Omron CX-Programmer project NuevoProyecto (CX-Programmer 9.50)

# PLC NewPLC1: CQM1 CPU21

## Global symbols (name address type ; comment)
15.00 BOOL  ; CNT<3
15.01 BOOL  ; CNT=3

## Program P9_2 (no task)
Local symbols
CNT 15.00 BOOL  ; Salida contador
DN1 0.01 BOOL  ; Detector de nivel inferior depósito A
DN2 0.02 BOOL  ; Detector de nivel superior depósito A
DN3 0.03 BOOL  ; Detector de nivel inferior depósito B
DN4 0.04 BOOL  ; Detector de nivel superior depósito B
Etapa_0 10.00 BOOL
Etapa_1 10.01 BOOL
Etapa_10 10.10 BOOL
Etapa_11 10.11 BOOL
Etapa_2 10.02 BOOL
Etapa_3 10.03 BOOL
Etapa_4 10.04 BOOL
Etapa_5 10.05 BOOL
Etapa_6 10.06 BOOL
Etapa_7 10.07 BOOL
Etapa_8 10.08 BOOL
Etapa_9 10.09 BOOL
F1 0.05 BOOL  ; Final carrera izquierda
F2 0.06 BOOL  ; Final carrera derecha
KVD 100.05 BOOL  ; Contactor Vagoneta para giro a Derechas
KVI 100.06 BOOL  ; Contactor Vagoneta para giro a Izquierdas
PM 0.00 BOOL  ; Pulsador de marcha
Salidas_deco 101 CHANNEL  ; Salidas para el decodificador (solo se usaran los dos bits de menos peso ya que la cuenta es hasta 3)
VA1 100.00 BOOL  ; Válvula llenado depósito A
VA2 100.02 BOOL  ; Válvula vaciado depósito A
VB1 100.01 BOOL  ; Válvula llenado depósito B
VB2 100.03 BOOL  ; Válvula vaciado depósito B
VC 100.04 BOOL  ; Válvula vaciado depósito C (vagoneta)

### Section Sección1_Programa_principal
; Programa principal (Etapas 0 ... 11)

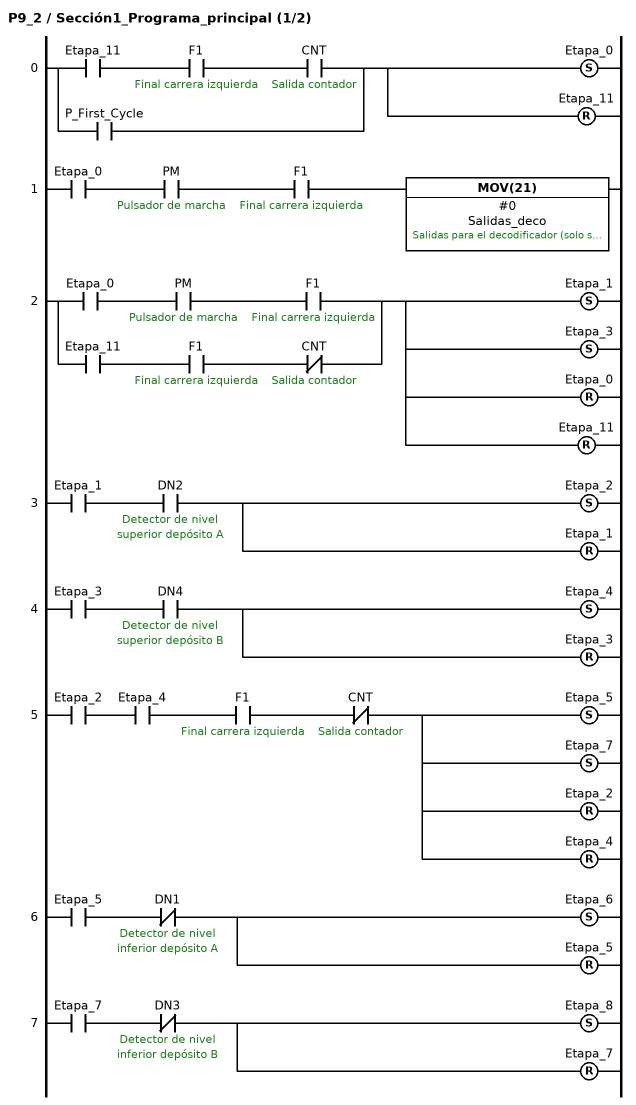
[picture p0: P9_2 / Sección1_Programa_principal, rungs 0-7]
; rung 0
LD Etapa_11
AND F1  ; Final carrera izquierda
AND CNT  ; Salida contador  // Cuando la vagoneta se vacíe 3 veces, la variable CNT pasará a 1  (ver Sección3_Contador_y_Salidas_deco)
OR P_First_Cycle
SET Etapa_0
RSET Etapa_11
; rung 1
LD Etapa_0
AND PM  ; Pulsador de marcha
AND F1  ; Final carrera izquierda
MOV(21) #0 Salidas_deco  ; Salidas para el decodificador (solo se usaran los dos bits de menos peso ya que la cuenta es hasta 3)  // El display se reseteará al activar PM, Siempre y cuando se hayan realizado los tres viajes y esté en F1
; rung 2
LD Etapa_0
AND PM  ; Pulsador de marcha
AND F1  ; Final carrera izquierda
LD Etapa_11
AND F1  ; Final carrera izquierda
ANDNOT CNT  ; Salida contador
ORLD
SET Etapa_1
SET Etapa_3
RSET Etapa_0
RSET Etapa_11
; rung 3
LD Etapa_1
AND DN2  ; Detector de nivel superior depósito A
SET Etapa_2
RSET Etapa_1
; rung 4
LD Etapa_3
AND DN4  ; Detector de nivel superior depósito B
SET Etapa_4
RSET Etapa_3
; rung 5
LD Etapa_2
AND Etapa_4
AND F1  ; Final carrera izquierda
ANDNOT CNT  ; Salida contador
SET Etapa_5
SET Etapa_7
RSET Etapa_2
RSET Etapa_4
; rung 6
LD Etapa_5
ANDNOT DN1  ; Detector de nivel inferior depósito A
SET Etapa_6
RSET Etapa_5
; rung 7
LD Etapa_7
ANDNOT DN3  ; Detector de nivel inferior depósito B
SET Etapa_8
RSET Etapa_7

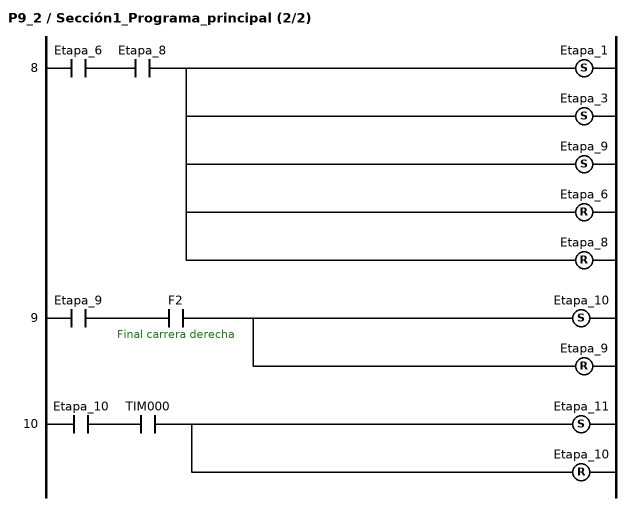
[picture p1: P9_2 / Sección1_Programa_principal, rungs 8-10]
; rung 8
LD Etapa_6
AND Etapa_8
SET Etapa_1
SET Etapa_3
SET Etapa_9
RSET Etapa_6
RSET Etapa_8
; rung 9
LD Etapa_9
AND F2  ; Final carrera derecha
SET Etapa_10
RSET Etapa_9
; rung 10
LD Etapa_10
AND TIM000
SET Etapa_11
RSET Etapa_10

### Section Sección2_Temporizador

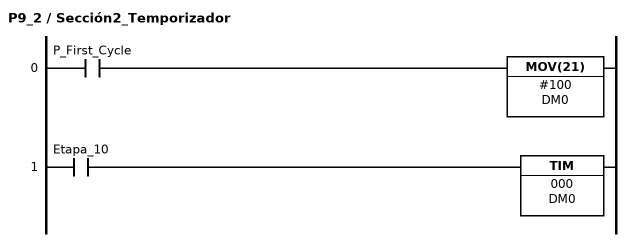
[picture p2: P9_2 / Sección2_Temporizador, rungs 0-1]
; rung 0
LD P_First_Cycle
MOV(21) #100 DM0
; rung 1
LD Etapa_10
TIM 000 DM0

### Section Sección3_Contador_y_Salidas_deco
; Contador ascendente realizado mediante @++, CMP y  KEEP

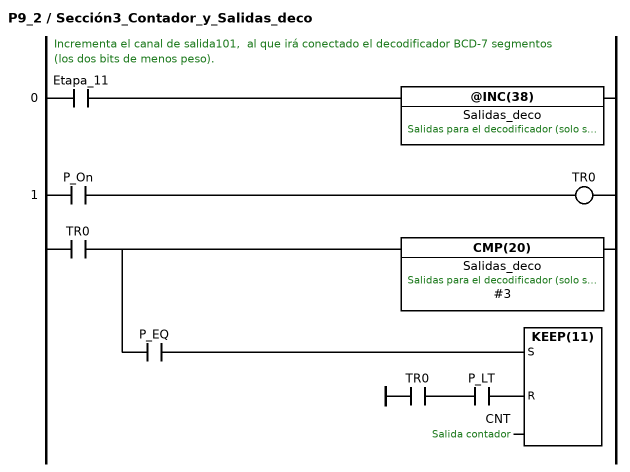
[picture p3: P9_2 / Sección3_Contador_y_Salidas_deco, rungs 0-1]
; rung 0: Incrementa el canal de salida101,  al que irá conectado el decodificador BCD-7 segmentos (los dos bits de menos peso).
LD Etapa_11
@INC(38) Salidas_deco  ; Salidas para el decodificador (solo se usaran los dos bits de menos peso ya que la cuenta es hasta 3)
; rung 1
LD P_On
OUT TR0
CMP(20) Salidas_deco #3  ; Salidas para el decodificador (solo se usaran los dos bits de menos peso ya que la cuenta es hasta 3)
AND P_EQ
LD TR0
AND P_LT
KEEP(11) CNT  ; Salida contador

### Section Sección4_Salidas_automatismo
; Salidas

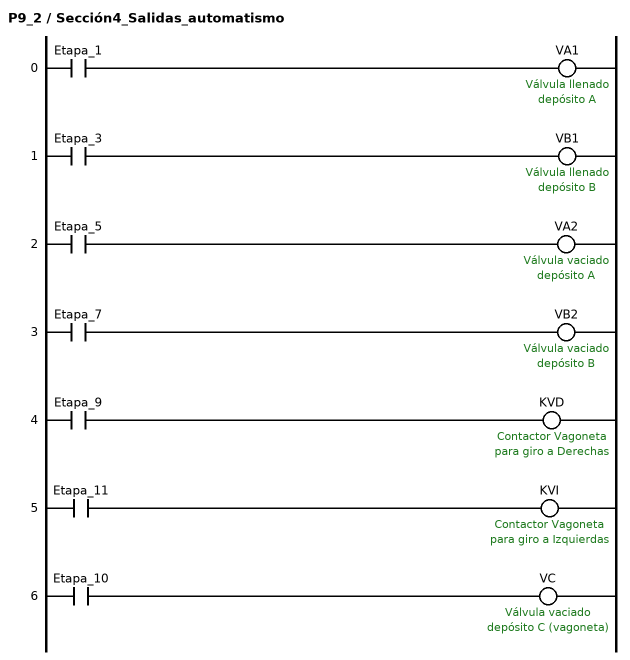
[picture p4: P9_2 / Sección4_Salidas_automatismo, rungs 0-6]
; rung 0
LD Etapa_1
OUT VA1  ; Válvula llenado depósito A
; rung 1
LD Etapa_3
OUT VB1  ; Válvula llenado depósito B
; rung 2
LD Etapa_5
OUT VA2  ; Válvula vaciado depósito A
; rung 3
LD Etapa_7
OUT VB2  ; Válvula vaciado depósito B
; rung 4
LD Etapa_9
OUT KVD  ; Contactor Vagoneta para giro a Derechas
; rung 5
LD Etapa_11
OUT KVI  ; Contactor Vagoneta para giro a Izquierdas
; rung 6
LD Etapa_10
OUT VC  ; Válvula vaciado depósito C (vagoneta)

### Section Sección5_END
; rung 0
END(01)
